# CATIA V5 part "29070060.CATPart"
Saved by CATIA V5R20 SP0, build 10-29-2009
Part number: 29070060
Definition: NONE
Nomenclature: 29070060
Source: Unknown
Description: 29070060
Bounding box of the stored display mesh (mm): x -30 to 44.548, y -49 to 83.548, z -39 to 39
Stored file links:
  C:\Users\Utente\Desktop\IO LAVORO\3D X SITO CF\X SITO\PLASTICA\RF1\29070060.CATPart
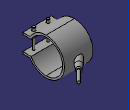
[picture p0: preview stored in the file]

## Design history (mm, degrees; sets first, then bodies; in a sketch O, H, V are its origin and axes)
Body1 "29070060" (main body)
  Solid1: solid without history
